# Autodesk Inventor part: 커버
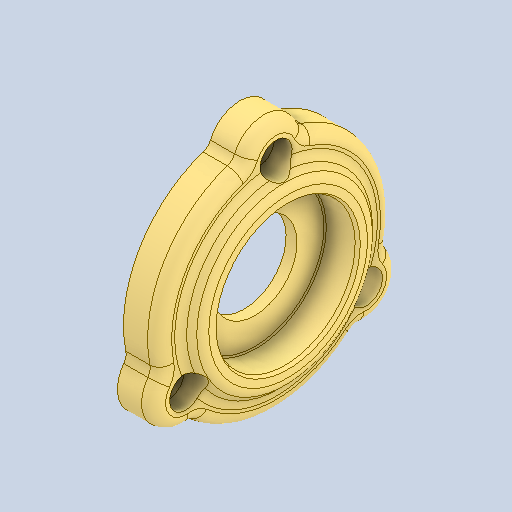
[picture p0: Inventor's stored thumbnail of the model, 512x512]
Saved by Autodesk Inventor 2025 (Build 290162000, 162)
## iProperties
Created: 2026-03
Part Number: 커버
Material: 알루미늄 6061
Document SubType Name: Modeling
Designer: KDI
Density: 2.7 g/cm^3
Appearance: 기본값
Author: jhkim
Sending System: Autodesk Inventor 2026
Preprocessor: ST-DEVELOPER v20.1
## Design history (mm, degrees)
feature "솔리드1"
node "솔리드2"
